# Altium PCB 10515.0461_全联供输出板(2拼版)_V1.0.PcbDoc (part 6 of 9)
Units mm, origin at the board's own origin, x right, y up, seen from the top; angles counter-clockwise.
Board outline 283.88 x 134.8 mm, 2 copper layers (Top Layer, Bottom Layer); 298 components, 0 nets, 1264 pads, 970 vias.
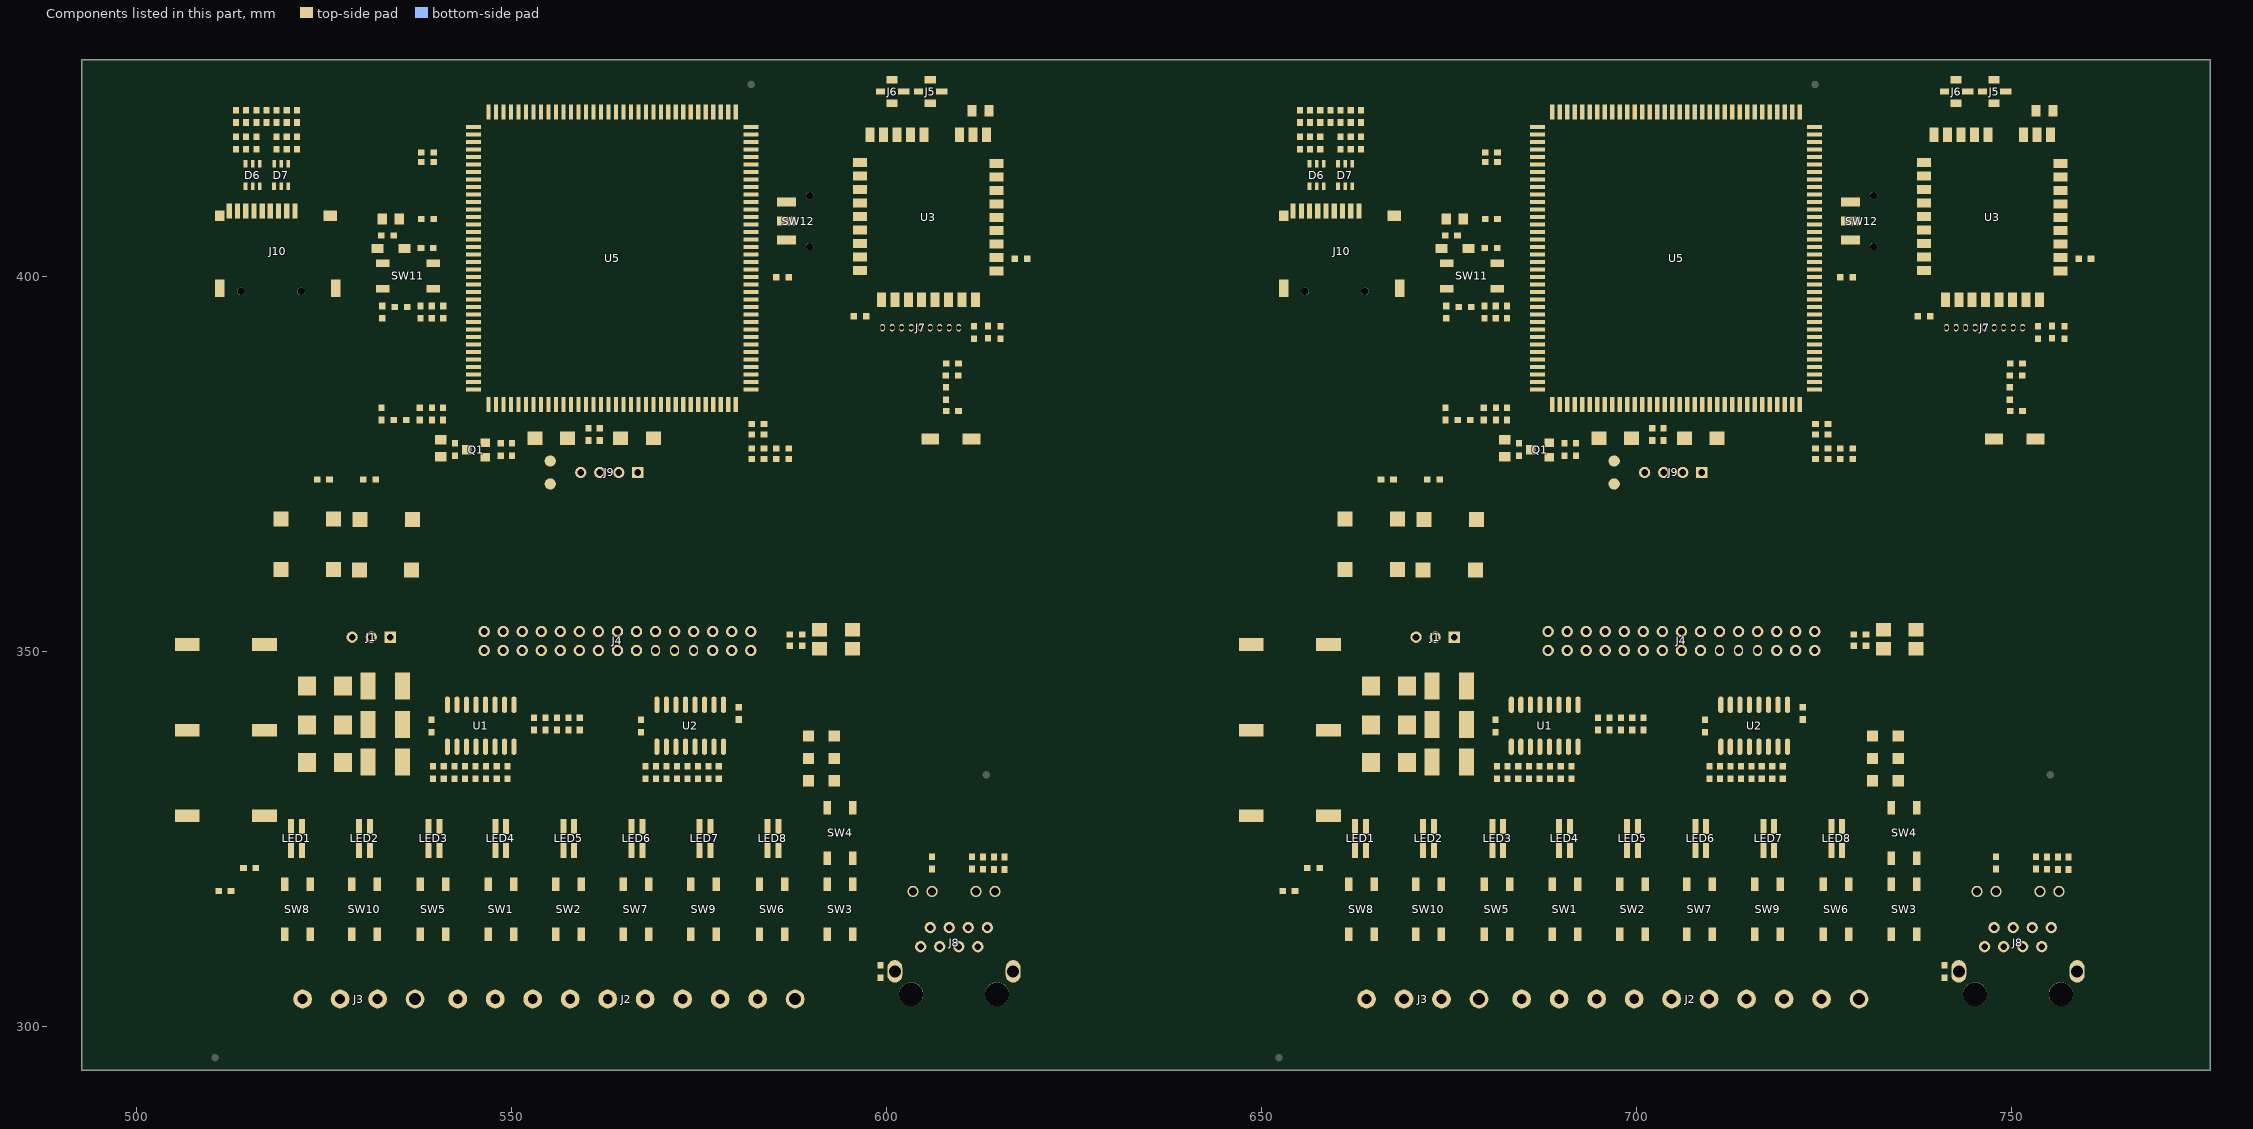
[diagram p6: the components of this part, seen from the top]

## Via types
v1: diameter 0.7, hole 0.4, Top Layer to Bottom Layer, tented both sides, 970 vias

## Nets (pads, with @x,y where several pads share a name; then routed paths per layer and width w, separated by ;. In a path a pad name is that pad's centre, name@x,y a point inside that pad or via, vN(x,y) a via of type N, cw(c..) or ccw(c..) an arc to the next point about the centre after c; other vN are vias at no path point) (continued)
copper on no net: (continued)
  Top Layer w0.8: 506.399,328.353 ccw(c505.631,329.121) 506.717,329.121 ccw(c507.803,329.121) 507.035,328.353 ; 506.399,339.147 cw(c505.631,338.379) 506.717,338.379 cw(c507.803,338.379) 507.035,339.147 ; 506.399,339.783 ccw(c505.631,340.551) 506.717,340.551 ccw(c507.803,340.551) 507.035,339.783 ; 506.399,350.577 cw(c505.631,349.809) 506.717,349.809 cw(c507.803,349.809) 507.035,350.577 ; v1@506.807,348.943 ccw(c507.913,348.943) 507.131,348.161 ; 507.199,339.147 cw(c505.878,337.826) 507.746,337.826 ; 507.199,339.783 ccw(c505.878,341.104) 507.746,341.104 ; 507.227,328.379 ccw(c506.061,329.766) 507.873,329.766 507.873,328.877 507.031,328.035 506.717,328.035 ; 507.364,328.35 cw(c507.978,327.086) 508.971,328.08 ; 507.517,350.445 cw(c507.517,349.532) 508.162,350.178 ; 507.613,327.595 cw(c507.828,326.618) 508.535,327.326 ; 507.746,329.766 507.746,344.879 ; 507.746,346.53 507.746,347.546 ; 507.835,327.717 cw(c508.603,326.949) 508.603,328.035 cw(c508.603,329.121) 507.835,328.353 ; 507.873,329.178 509.016,328.035 ; 507.873,344.879 510.032,347.038 ; 507.877,328.305 ccw(c509.524,329.536) 509.524,327.48 ; 507.967,350.895 ccw(c509.227,350.895) 508.336,350.004 ; 507.98,346.764 cw(c508.762,345.982) v1@508.762,347.088 ; 508,346.784 cw(c508.735,346.049) v1@508.763,347.088 ; 508,347.292 ccw(c508.735,348.027) v1@508.763,346.988 ; 508.817,349.523 cw(c507.601,348.308) v1@509.32,348.308 ; v1@509.27,348.358 cw(c509.27,346.639) 510.485,347.855 ; 509.668,346.674 cw(c510.667,345.676) v1@510.667,347.088 ; 509.715,346.721 cw(c510.605,345.83) v1@510.67,347.088 ; 509.848,348.492 ccw(c510.413,349.057) v1@510.413,348.258 ; v1@510.109,328.035 ccw(c511.083,328.035) 510.394,327.346 ; v1@510.163,328.085 cw(c510.107,327.298) 510.896,327.298 ; v1@510.194,328.07 cw(c508.501,326.377) 510.896,326.377 ; v1@510.208,328.024 cw(c509.524,328.182) 509.524,327.48 ; 510.286,303.731 510.286,304.366 ; 510.286,316.61 cw(c512.253,316.61) 510.862,318 ; 510.286,317.169 cw(c511.173,317.169) 510.86,317.999 ; 510.286,319.4 ccw(c512.253,319.4) 510.862,318.01 ; v1@510.286,348.054 507.445,350.895 506.717,350.895 506.717,348.575 507.746,347.546 ; 510.858,318.011 cw(c510.89,318.615) 510.286,318.615 ; 510.896,326.845 510.261,327.48 509.524,327.48 ; 511.048,398.408 511.048,406.601 ; 511.048,408.06 511.048,406.601 ; v1(511.429,347.038) 508.254,347.038 ; 512.699,300.937 510.286,303.35 510.286,302.588 ; 513.08,336.37 513.842,337.132 ; 513.842,300.937 536.321,300.937 537.09,301.706 ; v1(514.223,323.035) 514.223,308.176 ; 514.789,307.61 cw(c514.338,307.16) v1@514.975,307.16 ; v1@514.881,307.138 ccw(c515.874,307.637) 515.874,306.525 ; v1@514.904,307.115 cw(c515.39,308.176) 514.223,308.176 ; v1@514.925,307.21 cw(c514.925,306.573) 515.376,307.023 ; 515.377,338.667 cw(c516.217,337.827) 516.217,339.015 ; 515.479,338.769 ccw(c514.782,339.465) 515.767,339.465 ; 515.707,338.783 ccw(c515.707,339.691) 516.537,339.323 ; 515.806,339.647 cw(c514.477,340.236) 514.477,338.783 ; 515.849,326.81 cw(c516.725,326.81) 516.389,327.619 ; 515.849,330.011 ccw(c518.193,330.011) 516.535,328.353 ; 515.874,339.173 ccw(c513.969,337.55) 513.969,340.053 ; 515.882,321.058 ccw(c514.369,322.571) 516.509,322.571 ; 515.886,321.059 ccw(c515.854,321.713) 516.509,321.713 ; 515.893,321.053 ccw(c517.041,321.053) 516.229,320.241 ; 515.899,328.353 ccw(c514.732,329.52) 516.382,329.52 ; 515.899,339.147 ccw(c515.131,338.379) 515.131,339.465 ccw(c515.131,340.551) 515.899,339.783 ; 516.382,327.606 516.382,333.576 ; 516.699,328.353 ccw(c515.931,329.121) 517.017,329.121 ccw(c518.103,329.121) 517.335,328.353 ; 516.699,350.577 cw(c515.931,349.809) 517.017,349.809 cw(c518.103,349.809) 517.335,350.577 ; 517.271,332.814 519.049,334.592 ; 517.499,328.353 ccw(c516.822,329.03) 517.779,329.03 ; 517.499,350.577 cw(c516.822,349.9) 517.779,349.9 ; 517.525,308.049 516.636,308.938 516.636,319.835 515.849,320.622 ; 517.57,339.712 cw(c519.925,337.357) 519.925,340.688 ; 517.779,329.213 ccw(c518.995,329.213) 518.135,328.353 ; 517.779,347.927 519.811,345.895 ; 517.779,349.717 cw(c518.995,349.717) 518.135,350.577 ; 517.951,338.91 ccw(c517.951,344.765) 522.091,340.625 ; 517.976,351.316 ccw(c518.232,351.999) 518.748,351.483 ; 518.135,351.213 ccw(c518.903,351.981) 518.903,350.895 ccw(c518.903,349.809) 518.135,350.577 ; 518.267,339.465 cw(c519.945,339.465) 518.758,340.651 ; 518.668,345.336 517.779,346.225 517.779,347.419 ; 519.068,367.726 cw(c520.062,367.037) 520.062,368.247 ; 519.238,335.862 cw(c519.238,331.828) 522.091,334.681 ; 519.238,346.022 cw(c519.238,341.988) 522.091,344.841 ; 519.291,339.465 ccw(c519.291,343.425) 522.091,340.625 ; 519.373,361.022 cw(c517.704,359.353) 520.065,359.353 ; 519.484,334.592 ccw(c519.484,338.279) 522.091,335.672 ; 519.484,344.752 ccw(c519.484,348.439) 522.091,345.832 ; 519.545,340.688 cw(c519.545,337.088) 522.091,339.634 ; 519.656,360.457 ccw(c520.681,359.432) 519.232,359.432 ccw(c517.783,359.432) 518.808,360.457 ; 519.656,361.305 cw(c520.681,362.33) 519.232,362.33 cw(c517.783,362.33) 518.808,361.305 ccw(c516.692,363.421) 519.684,363.421 ; 519.656,368.036 ccw(c520.681,369.061) 520.681,367.612 ccw(c520.681,366.163) 519.656,367.188 ccw(c520.681,366.163) 519.232,366.163 ccw(c517.783,366.163) 518.808,367.188 cw(c516.692,365.072) 519.684,365.072 ; 519.684,358.341 ccw(c516.692,358.341) 518.808,360.457 ; 519.684,367.612 519.684,354.531 ; 519.725,367.271 cw(c521.589,365.981) 521.589,368.247 ; 519.882,338.91 ccw(c519.882,342.834) 522.656,340.059 cw(c521.222,341.494) 521.222,339.465 ; 520.065,357.421 ccw(c515.772,357.421) 518.808,360.457 ; 520.243,338.91 cw(c520.243,341.891) 518.135,339.783 ccw(c518.903,340.551) 518.903,339.465 ccw(c518.903,338.379) 518.135,339.147 ; 520.323,340.053 ccw(c520.323,336.959) 518.135,339.147 ; 520.323,351.483 ccw(c520.323,348.389) 518.135,350.577 ; 520.71,340.053 ccw(c520.71,342.006) 522.091,340.625 ; 520.74,340.053 cw(c520.74,338.143) 522.091,339.494 ; 521.17,335.862 cw(c521.17,333.76) 522.656,335.246 ; 521.17,346.022 cw(c521.17,343.92) 522.656,345.406 ; 521.415,334.592 ccw(c521.415,336.348) 522.656,335.106 ; 521.415,344.752 ccw(c521.415,346.508) 522.656,345.266 ; 521.437,338.91 517.572,338.91 517.017,339.465 ; 521.462,356.288 cw(c521.921,356.288) v1@521.833,356.739 ; 521.462,356.6 cw(c523.076,356.6) 521.935,357.741 cw(c522.769,356.907) 522.769,358.087 ; 521.462,357.489 ccw(c522.642,357.489) v1@521.808,356.655 ; 521.476,340.688 cw(c521.476,339.019) 522.656,340.199 ; 521.813,338.91 ccw(c521.813,340.902) 523.222,339.494 ; 521.856,340.688 ccw(c521.856,335.426) 518.135,339.147 ; 521.971,335.862 518.668,335.862 517.652,334.846 ; 521.971,346.022 518.668,346.022 517.779,346.911 517.779,347.419 ; v1(521.97,357.706) v1@521.97,356.563 ; v1(521.97,410.538) 527.431,410.538 ; v1@522.016,357.726 ccw(c521.462,357.482) 521.462,358.087 ; 522.072,334.592 519.049,334.592 ; 522.072,344.752 517.779,344.752 517.017,345.514 517.017,346.657 ; 522.09,303.604 514.858,303.604 ; 522.091,334.611 ccw(c520.725,333.245) 520.725,335.176 ccw(c520.725,337.108) 522.091,335.742 ; 522.091,344.771 ccw(c520.725,343.405) 520.725,345.336 ccw(c520.725,347.268) 522.091,345.902 ; 522.098,340.688 518.795,340.688 517.572,339.465 517.017,339.465 ; 522.187,358.087 cw(c522.187,356.907) v1@523.021,357.741 ; 522.58,340.053 518.414,340.053 ; 522.656,335.176 517.982,335.176 517.652,334.846 ; 522.656,340.129 521.992,339.465 517.017,339.465 ; 522.656,345.336 517.83,345.336 517.017,346.149 517.017,346.657 ; v1@522.951,357.741 cw(c523.785,356.907) 523.785,358.087 ; 523.255,356.563 ccw(c523.255,357.31) v1@523.783,356.782 ; 523.33,358.087 cw(c523.33,356.907) v1@524.164,357.741 ; 523.374,351.236 ccw(c522.776,350.638) 522.776,351.483 528.32,351.483 528.701,351.864 ; 523.494,370.152 523.494,372.386 524.027,372.919 ; 523.494,371.708 cw(c525.201,371.708) 523.994,372.915 ; 523.494,372.191 cw(c524.266,372.191) 523.992,372.913 ; 523.494,374.13 ccw(c525.201,374.13) 523.994,372.924 ; v1@523.713,356.782 ccw(c524.241,357.31) 524.241,356.563 ; 523.748,371.422 519.938,367.612 519.232,367.612 ; 524.027,370.685 521.589,368.247 ; 524.027,384.63 525.043,385.646 528.193,385.646 528.828,386.281 528.828,386.916 ; 524.856,358.56 ccw(c522.925,360.49) 525.636,360.81 ; 525.569,407.849 cw(c525.059,407.339) 525.78,407.339 cw(c526.501,407.339) 525.991,407.849 ; 525.678,368.466 ccw(c527.086,368.466) 526.091,367.471 ; 525.678,370.397 ccw(c529.017,370.397) 526.656,368.036 cw(c527.681,369.061) 526.232,369.061 cw(c524.783,369.061) 525.808,368.036 ccw(c523.115,370.729) 526.923,370.729 ; 525.678,372.438 526.923,371.193 526.923,361.897 ; 525.678,376.459 cw(c527.639,376.459) v1@526.253,377.845 ; 525.678,379.161 ccw(c527.639,379.161) v1@526.253,377.775 ; 525.712,372.924 ccw(c524.628,374.008) 526.161,374.008 ; 525.713,372.925 ccw(c525.252,373.708) 526.161,373.708 ; 525.78,361.333 525.78,367.612 526.232,367.612 ; 525.78,363.421 ccw(c528.772,363.421) 526.656,361.305 cw(c527.681,362.33) 526.232,362.33 cw(c524.783,362.33) 525.808,361.305 ccw(c523.115,363.998) 526.923,363.998 ; 525.78,365.072 cw(c528.772,365.072) 526.656,367.188 ccw(c527.681,366.163) 526.232,366.163 ccw(c524.783,366.163) 525.808,367.188 cw(c523.115,364.495) 526.923,364.495 ; 525.78,399.391 ccw(c527.018,399.391) 526.142,398.516 ; 525.78,401.088 cw(c527.394,401.088) v1@526.253,402.229 ; 525.78,401.323 ccw(c528.949,401.323) 526.708,399.082 ; 525.78,403.3 ccw(c527.394,403.3) v1@526.253,402.159 ; 525.78,403.628 cw(c527.394,403.628) v1@526.253,404.769 ; 525.78,405.84 ccw(c527.394,405.84) v1@526.253,404.699 ; 525.78,408.06 525.78,406.601 ; 525.971,373.518 ccw(c526.57,372.919) 525.723,372.919 ccw(c526.992,372.919) 526.095,372.022 ; 526.022,359.726 ccw(c525.011,360.737) 526.431,360.905 ; 526.042,382.733 cw(c526.542,382.233) v1@526.542,382.94 ; 526.161,351.483 526.542,351.864 528.701,351.864 ; 526.232,359.936 524.383,358.087 521.462,358.087 ; 526.232,371.884 526.232,367.612 ; 526.373,360.74 ccw(c525.047,362.066) 526.923,362.066 ; 526.373,367.471 ccw(c525.047,368.797) 526.923,368.797 ; 526.373,367.753 cw(c525.047,366.427) 526.923,366.427 ; 526.421,382.477 ccw(c526.008,382.89) v1@526.592,382.89 ; v1@526.492,382.887 cw(c527.1,382.929) 526.669,383.36 ; v1@526.507,382.925 cw(c527.556,381.876) 527.556,383.36 ; v1@526.542,382.84 ccw(c526.542,383.425) 526.955,383.011 ; 526.542,398.408 525.78,399.17 525.78,406.601 ; 526.78,361.125 cw(c527.413,361.407) 526.923,361.897 ; 527.05,386.281 528.193,387.424 528.193,395.044 529.184,396.035 532.715,396.035 ; 527.304,383.36 526.161,382.217 526.161,373.708 ; 527.456,335.246 cw(c528.672,334.471) 528.672,335.913 ; 527.456,345.336 528.041,344.752 530.182,344.752 ; 527.489,345.369 530.799,345.369 530.182,344.752 ; 528.022,334.611 cw(c529.388,333.245) 529.388,335.176 cw(c529.388,337.108) 528.022,335.742 ; 528.022,339.564 cw(c529.388,338.198) 529.388,340.129 cw(c529.388,342.061) 528.022,340.695 ; 528.022,344.771 cw(c529.466,343.327) 529.466,345.369 ; 528.022,345.902 ccw(c529.31,347.189) 529.31,345.369 ; 528.082,345.764 ccw(c530.182,347.435) 530.182,344.752 ; 528.088,340.551 ccw(c530.145,342.152) 530.145,339.545 528.041,339.545 527.456,340.129 530.729,340.129 ; 528.131,334.816 cw(c530.131,333.541) 530.131,335.913 528.193,335.913 527.456,335.176 530.729,335.176 ; 528.828,409.268 527.558,410.538 527.431,410.538 ; 528.907,344.752 cw(c528.907,342.677) 530.374,344.144 ; 528.955,403.68 532.108,403.68 532.574,404.146 532.574,407.503 ; 528.963,383.241 cw(c529.463,382.741) v1@529.463,383.448 ; 528.996,339.545 cw(c528.996,337.596) 530.374,338.974 ; 529.03,335.913 ccw(c529.03,337.814) 530.374,336.47 ; 529.183,335.176 ccw(c529.183,336.861) 530.374,335.67 ; 529.183,340.129 ccw(c529.183,341.814) 530.374,340.623 ; 529.209,361.241 529.209,371.878 530.2,372.869 ; 529.209,363.308 ccw(c532.15,363.308) 530.07,361.228 cw(c531.095,362.253) 529.646,362.253 cw(c528.197,362.253) 529.222,361.228 ccw(c526.8,363.65) 530.225,363.65 ; 529.209,364.725 cw(c532.583,364.725) 530.197,367.111 ccw(c531.528,365.78) 529.646,365.78 ; 529.209,366.656 cw(c530.652,366.656) 529.632,367.676 ; 529.209,368.414 ccw(c530.652,368.414) 529.632,367.394 ; 529.209,370.345 ccw(c532.583,370.345) 530.197,367.959 cw(c531.222,368.984) 529.773,368.984 cw(c528.324,368.984) 529.349,367.959 ccw(c527.295,370.013) 530.2,370.013 ; 529.244,360.359 cw(c527.249,358.15) 530.225,358.15 ; v1(529.336,397.838) v1(528.828,398.346) 528.828,410.03 528.32,410.538 527.431,410.538 ; v1@529.413,383.398 cw(c530.12,383.398) 529.62,383.898 ; 529.517,335.176 cw(c529.517,333.964) 530.374,334.821 ; 529.517,340.129 cw(c529.517,338.917) 530.374,339.774 ; v1@529.54,374.474 ccw(c530.717,374.378) 529.882,373.543 ; 529.59,373.59 cw(c530.612,373.59) v1@530.178,374.515 ; 529.59,373.754 cw(c531.551,373.754) v1@530.164,375.14 ; 529.59,375.821 ccw(c531.551,375.821) v1@530.164,374.435 ; 529.59,376.456 ccw(c531.551,376.456) v1@530.164,375.07 ; v1@529.625,374.435 ccw(c528.239,375.821) 530.2,375.821 ; v1@529.625,374.505 cw(c528.239,373.119) 530.2,373.119 ; v1@529.625,375.07 ccw(c528.239,376.456) 530.2,376.456 ; v1@529.625,375.14 cw(c528.239,373.754) 530.2,373.754 ; 529.646,366.393 ccw(c528.631,366.393) 529.349,367.111 cw(c527.233,364.995) 530.225,364.995 ; 529.67,335.913 cw(c529.67,334.917) 530.374,335.621 ; 529.704,339.545 ccw(c529.704,340.493) 530.374,339.823 ; 529.773,371.916 cw(c531.115,371.916) 530.166,372.864 ; 529.773,372.292 cw(c530.386,372.292) 530.164,372.863 ; 529.78,360.952 cw(c528.875,359.951) 530.225,359.951 ; 529.787,360.663 ccw(c528.731,361.719) 530.225,361.719 ; 529.793,344.752 ccw(c529.793,345.574) 530.374,344.993 ; 529.872,373.553 cw(c529.187,372.869) 530.155,372.869 ; 530.225,368.476 530.225,361.383 ; 530.352,385.265 529.209,384.122 526.542,384.122 525.678,383.258 525.678,382.369 ; 530.352,386.134 cw(c531.328,386.134) v1@530.638,386.824 ; 530.352,387.444 ccw(c531.328,387.444) v1@530.638,386.754 ; 530.352,392.103 cw(c531.328,392.103) v1@530.638,392.793 ; 530.352,393.413 ccw(c531.328,393.413) v1@530.638,392.723 ; 530.374,344.944 ccw(c529.35,343.92) 529.35,345.369 ccw(c529.35,346.817) 530.374,345.793 ; v1@530.709,386.754 ccw(c530.343,387.119) 530.86,387.119 ; v1@530.709,386.824 cw(c530.343,386.459) 530.86,386.459 ; v1@530.709,392.723 ccw(c530.343,393.088) 530.86,393.088 ; v1@530.709,392.793 cw(c530.343,392.428) 530.86,392.428 ; 531.622,394.384 530.86,393.622 530.86,385.138 530.352,384.63 ; 531.851,379.804 532.638,380.591 532.638,380.82 ; 531.893,372.864 cw(c533.623,371.135) 533.623,373.581 ; 531.895,372.867 ccw(c532.662,372.652) 532.099,372.088 ; 532.167,403.821 ccw(c531.182,404.806) 532.574,404.806 ; 532.574,406.611 cw(c533.619,406.611) 532.88,407.349 ; 532.633,382.514 ccw(c530.783,384.364) 533.4,384.364 ; 532.793,398.348 539.493,398.348 541.149,398.348 541.528,398.727 541.528,403.172 540.943,403.757 539.521,403.757 ; 532.793,401.748 539.493,401.748 ; v1(533.4,392.758) 533.4,382.471 ; 534.226,405.458 535.305,405.458 535.708,405.055 535.708,403.68 ; 534.231,380.82 531.851,380.82 531.851,373.581 ; 534.264,396.035 532.715,396.035 ; 534.797,354.102 534.241,354.658 520.652,354.658 520.065,355.245 520.065,360.048 519.232,360.881 ; 534.974,346.593 ccw(c533.95,347.617) 535.399,347.617 ccw(c536.847,347.617) 535.823,346.593 ; 535,407.642 537.883,407.642 ; 535.399,345.369 535.399,348.275 537.21,350.086 ; 535.785,403.757 537.87,403.757 537.87,401.9 ; 535.925,368.12 cw(c535.925,366.793) 536.924,367.667 ; 535.947,380.82 537.718,380.82 539.33,380.82 540.816,380.82 ; 536.049,403.539 cw(c536.577,403.011) 536.577,403.757 ; 536.169,396.035 537.795,396.035 539.319,396.035 540.843,396.035 ; 536.194,358.264 cw(c539.186,358.264) 537.07,360.38 ccw(c538.095,359.355) 536.646,359.355 ccw(c535.197,359.355) 536.222,360.38 ; 536.194,363.344 ccw(c539.186,363.344) 537.07,361.228 cw(c537.788,361.946) 536.773,361.946 ; 536.194,364.689 cw(c539.619,364.689) 537.197,367.111 ccw(c538.222,366.086) 536.773,366.086 ccw(c535.324,366.086) 536.349,367.111 ccw(c535.324,366.086) 535.324,367.535 ccw(c535.324,368.984) 536.349,367.959 ; 536.194,366.62 cw(c537.688,366.62) 536.632,367.676 ; 536.194,366.956 536.194,355.928 536.448,355.674 539.115,355.674 551.18,355.674 ; 536.222,361.228 ccw(c534.891,362.559) 536.773,362.559 ; 536.321,367.14 ccw(c534.162,365.251) 534.162,368.12 ; 536.524,302.97 cw(c535.396,301.706) 537.09,301.706 ; 537.039,355.845 538.944,355.845 553.041,355.845 553.212,355.674 ; 537.09,303.604 537.09,301.706 ; 537.21,356.309 536.646,356.873 536.646,360.804 536.773,360.931 536.773,367.535 ; v1@537.265,339.594 cw(c537.451,338.838) 538.002,339.388 ; v1@537.277,339.595 cw(c537.277,338.345) 538.161,339.229 ; v1@537.311,339.508 ccw(c536.462,340.434) 537.718,340.434 ; 537.656,302.97 ccw(c538.784,301.706) 537.09,301.706 ; 537.718,340.09 cw(c538.668,340.09) v1@537.996,340.761 ; 537.718,340.118 cw(c538.601,340.118) v1@537.997,340.763 ; 537.718,341.362 ccw(c538.668,341.362) v1@537.996,340.691 ; 537.718,345.939 cw(c538.56,345.939) v1@538.205,346.702 ; 537.795,394.384 540.843,394.384 532.715,394.384 531.089,394.384 530.352,393.647 530.352,384.63 ; v1@537.983,340.737 ccw(c539.189,340.479) 538.317,339.607 ; v1@538.176,346.657 cw(c540.508,346.657) v1@538.859,348.306 ; v1@538.221,346.607 cw(c538.279,347.165) v1@537.718,347.165 ; 538.263,339.66 ccw(c539.292,340.688) 539.292,339.234 ; 538.624,348.071 cw(c539.623,347.073) v1@539.623,348.485 ; 538.64,348.087 ccw(c538.291,348.435) v1@538.784,348.435 ; v1@538.671,348.118 cw(c539.561,347.227) v1@539.626,348.485 ; 538.734,339.189 537.718,340.205 537.718,340.434 ; v1@538.816,347.397 cw(c539.627,347.796) v1@538.988,348.435 ; 539.292,339.189 538.201,339.189 537.718,339.672 537.718,340.434 ; 539.292,340.84 539.292,345.945 540.131,346.784 552.783,346.784 553.926,347.927 ; 539.292,345.26 540.308,346.276 540.766,346.276 ; 539.439,347.87 ccw(c538.874,348.435) v1@539.673,348.435 ; 539.623,346.276 540.766,346.276 ; 540.048,371.251 553.212,371.251 553.847,370.616 ; 540.537,378.204 540.537,380.541 ; 540.537,380.094 cw(c541.504,380.094) 540.821,380.777 ; 541.013,398.212 cw(c542.163,397.061) v1@542.163,398.688 ; 541.166,398.365 cw(c541.982,397.549) v1@542.171,398.687 ; 541.274,370.787 538.48,373.581 531.851,373.581 ; 541.528,400.05 ccw(c543.575,400.05) v1@542.128,398.603 ; 542.373,382.471 ccw(c542.373,383.218) v1@542.901,382.69 ; 542.777,303.604 542.777,307.054 541.782,308.049 516.763,308.049 515.849,308.963 515.849,320.622 ; v1@542.83,382.69 ccw(c543.358,383.218) 543.358,382.471 ; v1@544.576,382.725 544.322,382.471 540.816,382.471 539.33,382.471 537.718,382.471 533.4,382.471 ; v1(546.481,379.169) 546.481,377.817 546.59,377.709 548.513,377.709 ; 546.666,377.938 ccw(c547.221,378.493) 547.221,377.709 ; 551.024,352.626 ccw(c550.15,352.626) 550.768,353.244 ccw(c551.386,353.862) 551.386,352.988 ; 551.718,300.683 cw(c551.718,299.503) v1@552.553,300.337 ; v1@552.482,300.337 cw(c553.316,299.503) 553.316,300.683 ; 552.706,378.053 cw(c551.853,377.2) 553.06,377.2 cw(c554.267,377.2) 553.414,378.053 ; 552.958,341.133 554.482,341.133 556.006,341.133 557.53,341.133 559.054,341.133 ; v1@553.06,376.756 553.06,378.407 ; 553.094,353.76 cw(c551.961,352.626) 553.564,352.626 ; 553.67,349.83 cw(c553.052,349.212) 553.926,349.212 cw(c554.8,349.212) 554.182,349.83 ; 553.67,352.882 ccw(c553.052,353.5) 553.926,353.5 ccw(c554.8,353.5) 554.182,352.882 ; 553.926,350.086 553.926,347.244 552.958,346.276 540.766,346.276 ; 553.926,352.626 553.926,352.928 ; 557.208,302.973 cw(c556.052,301.692) 557.777,301.692 ; 557.777,303.604 557.777,301.692 ; 558.346,302.973 ccw(c559.502,301.692) 557.777,301.692 ; 564.014,374.082 ccw(c563.416,374.68) 564.261,374.68 ccw(c565.106,374.68) 564.508,374.082 ; 564.261,373.835 564.261,375.359 564.896,375.994 565.658,375.994 ; 564.511,374.08 cw(c564.903,374.463) 564.515,374.851 565.658,375.994 ; 564.611,373.835 cw(c567.296,373.835) 565.397,375.733 ; 567.048,374.082 ccw(c567.646,374.68) 567.646,373.835 ccw(c567.646,372.99) 567.048,373.588 ; 567.119,374.153 cw(c566.354,373.388) 567.436,373.388 ; v1@567.278,375.955 ccw(c567.589,376.349) 567.944,375.994 v1@568.858,376.908 ; v1@567.309,375.944 ccw(c567.309,377.356) 568.308,376.358 ; v1@567.401,376.086 cw(c568.833,374.653) 568.833,376.679 ccw(c568.833,376.186) 568.485,376.535 ; v1@567.421,375.994 ccw(c567.421,378.041) v1@568.868,376.594 ; 567.436,371.457 ccw(c564.423,371.457) 566.554,373.588 ; v1@567.754,376.439 cw(c568.486,375.706) v1@568.851,376.676 ; v1@567.898,376.609 ccw(c568.833,377.012) v1(568.833,375.994) ; v1@567.939,376.579 ccw(c568.051,377.715) v1@568.858,376.908 ; v1@567.979,376.594 ccw(c567.451,377.122) 568.198,377.122 ; v1@567.987,376.604 cw(c566.928,377.219) 566.928,375.994 ; 568.071,373.835 567.436,373.2 567.436,371.295 566.757,370.616 565.023,370.616 ; v1@568.198,376.783 cw(c569.471,376.783) 568.959,377.949 ; v1@568.793,375.964 cw(c569.367,376.399) v1@568.858,376.908 ; v1@568.804,376.588 cw(c569.609,377.747) 568.198,377.747 568.198,376.883 v1(567.309,375.994) 566.928,375.994 ; 583.629,375.613 v1(584.454,375.613) 585.279,375.613 ; 583.629,377.01 v1(584.454,377.01) 585.279,377.01 ; 586.93,377.01 586.93,375.613 586.93,374.407 ; 587.132,374.407 cw(c587.132,372.576) v1@588.426,373.87 ; 587.703,373.835 ccw(c587.703,375.666) v1@588.998,374.371 ; 587.767,374.407 cw(c587.767,372.576) v1@589.061,373.87 ; v1@588.341,373.84 cw(c588.962,373.783) v1(588.962,374.407) ; v1@588.752,374.617 cw(c587.97,373.835) v1@589.076,373.835 ; v1@601.041,373.84 cw(c601.599,373.782) 601.599,374.343 ; v1@601.056,373.87 cw(c602.197,372.729) v1@602.197,374.343 ; 601.074,307.285 616.864,307.285 ; v1@601.168,371.427 cw(c601.726,371.369) v1@601.726,371.93 ; v1@601.183,371.457 cw(c602.324,370.316) v1@602.324,371.93 ; v1@601.382,371.422 ccw(c601.382,373.036) v1@602.523,371.895 ; 601.498,306.861 cw(c602.523,305.836) 602.523,307.285 cw(c602.523,308.734) 601.498,307.709 ; v1@601.564,371.895 ccw(c602.705,373.036) 602.705,371.422 ; v1@601.818,373.87 cw(c602.959,372.729) 602.959,374.343 ; v1@601.945,371.457 cw(c603.086,370.316) 603.086,371.93 ; v1@602.072,374.435 ccw(c603.519,375.882) 603.519,373.835 ; v1@602.15,374.445 cw(c601.091,375.06) v1(601.091,373.835) ; v1@602.453,371.895 ccw(c603.594,373.036) 603.594,371.422 ; 605.006,378.179 cw(c606.783,378.348) 605.52,379.61 ; 605.058,371.93 cw(c605.058,370.75) v1@605.893,371.584 ; 605.155,376.981 cw(c606.666,376.981) 605.597,378.05 ; 605.155,377.772 605.155,379.244 ; 605.526,378.6 cw(c605.901,379.244) 605.155,379.244 ; 605.553,378.05 cw(c604.955,377.452) 605.8,377.452 cw(c606.645,377.452) 606.047,378.05 ; 605.553,378.544 ccw(c604.955,379.142) 605.8,379.142 ccw(c606.645,379.142) 606.047,378.544 ; 605.802,378.254 cw(c608.977,378.556) 606.722,380.811 ; v1@605.822,371.584 cw(c606.656,370.75) 606.656,371.93 ; 606.25,378.647 ccw(c606.25,380.262) 607.392,379.12 ; 606.513,380.019 ccw(c608.236,378.297) 605.8,378.297 ; 606.569,378.297 607.924,379.652 v1(607.924,380.693) ; 606.598,378.33 cw(c611.172,378.764) 607.923,382.013 ; 606.752,380.258 cw(c607.924,379.085) v1@607.924,380.743 ; 607.166,379.663 ccw(c608.531,378.297) 606.6,378.297 cw(c610.967,378.297) 607.879,381.385 ; 607.435,380.941 ccw(c606.363,382.013) 607.879,382.013 ; 607.876,385.202 607.876,388.315 ; v1@607.885,380.661 cw(c608.329,381.024) 607.924,381.43 605.8,379.306 605.8,378.297 ; 607.924,383.503 607.924,382.013 ; 609.335,381.085 cw(c606.548,378.297) 610.49,378.297 ccw(c608.559,378.297) 609.924,379.663 ; 609.575,380.845 611.29,379.13 ; 609.6,388.388 609.575,388.363 609.575,382.013 ; 609.619,382.013 ccw(c610.767,382.013) 609.955,381.201 ; v1@609.957,374.435 ccw(c608.364,376.027) 610.616,376.027 ; v1@609.957,374.505 cw(c608.364,372.913) 610.616,372.913 ; 610.18,380.976 cw(c607.501,378.297) 611.29,378.297 ; 610.616,376.911 cw(c612.226,376.911) 611.087,378.05 ; 610.616,378.971 610.616,373.073 609.473,371.93 609.092,371.93 ; 610.701,379.719 cw(c609.279,378.297) 611.29,378.297 ; 611.045,378.547 ccw(c610.474,379.13) 611.29,379.13 ; 611.124,377.051 cw(c612.536,377.051) 611.537,378.05 ; 611.493,378.05 cw(c610.91,377.467) 611.734,377.467 ; 611.493,378.544 ccw(c610.91,379.127) 611.734,379.127 ; 611.535,378.547 cw(c612.106,379.13) 611.29,379.13 ; 611.546,379.611 cw(c610.232,378.297) 612.09,378.297 ; 611.632,393.33 612.521,393.33 614.807,393.33 ; 611.734,377.437 cw(c612.6,377.437) 611.987,378.05 ; 611.734,379.157 ccw(c612.6,379.157) 611.987,378.544 ; 613.487,391.717 615.023,391.717 ; 616.44,306.861 ccw(c615.416,305.837) 615.416,307.285 ccw(c615.415,308.734) 616.44,307.709 ; 648.299,328.353 ccw(c647.531,329.121) 648.617,329.121 ccw(c649.703,329.121) 648.935,328.353 ; 648.299,339.147 cw(c647.531,338.379) 648.617,338.379 cw(c649.703,338.379) 648.935,339.147 ; 648.299,339.783 ccw(c647.531,340.551) 648.617,340.551 ccw(c649.703,340.551) 648.935,339.783 ; 648.299,350.577 cw(c647.531,349.809) 648.617,349.809 cw(c649.703,349.809) 648.935,350.577 ; v1@648.707,348.943 ccw(c649.813,348.943) 649.031,348.161 ; 649.099,339.147 cw(c647.778,337.826) 649.646,337.826 ; 649.099,339.783 ccw(c647.778,341.104) 649.646,341.104 ; 649.127,328.379 ccw(c647.961,329.766) 649.773,329.766 649.773,328.877 648.931,328.035 648.617,328.035 ; 649.264,328.35 cw(c649.878,327.086) 650.871,328.08 ; 649.417,350.445 cw(c649.417,349.532) 650.062,350.178 ; 649.513,327.595 cw(c649.728,326.618) 650.435,327.326 ; 649.646,329.766 649.646,344.879 ; 649.646,346.53 649.646,347.546 ; 649.735,327.717 cw(c650.503,326.949) 650.503,328.035 cw(c650.503,329.121) 649.735,328.353 ; 649.773,329.178 650.916,328.035 ; 649.773,344.879 651.932,347.038 ; 649.777,328.305 ccw(c651.424,329.536) 651.424,327.48 ; 649.867,350.895 ccw(c651.127,350.895) 650.236,350.004 ; 649.88,346.764 cw(c650.662,345.982) v1@650.662,347.088 ; 649.9,346.784 cw(c650.635,346.049) v1@650.663,347.088 ; 649.9,347.292 ccw(c650.635,348.027) v1@650.663,346.988 ; 650.717,349.523 cw(c649.501,348.308) v1@651.22,348.308 ; v1@651.17,348.358 cw(c651.17,346.639) 652.385,347.855 ; 651.568,346.674 cw(c652.567,345.676) v1@652.567,347.088 ; 651.615,346.721 cw(c652.505,345.83) v1@652.57,347.088 ; 651.748,348.492 ccw(c652.313,349.057) v1@652.313,348.258 ; v1@652.009,328.035 ccw(c652.983,328.035) 652.294,327.346 ; v1@652.063,328.085 cw(c652.007,327.298) 652.796,327.298 ; v1@652.094,328.07 cw(c650.401,326.377) 652.796,326.377 ; v1@652.108,328.024 cw(c651.424,328.182) 651.424,327.48 ; 652.186,303.731 652.186,304.366 ; 652.186,316.61 cw(c654.153,316.61) 652.762,318 ; 652.186,317.169 cw(c653.073,317.169) 652.76,317.999 ; 652.186,319.4 ccw(c654.153,319.4) 652.762,318.01 ; v1@652.186,348.054 649.345,350.895 648.617,350.895 648.617,348.575 649.646,347.546 ; 652.758,318.011 cw(c652.79,318.615) 652.186,318.615 ; 652.796,326.845 652.161,327.48 651.424,327.48 ; 652.948,398.408 652.948,406.601 ; 652.948,408.06 652.948,406.601 ; v1(653.329,347.038) 650.154,347.038 ; 654.599,300.937 652.186,303.35 652.186,302.588 ; 654.98,336.37 655.742,337.132 ; 655.742,300.937 678.221,300.937 678.99,301.706 ; v1(656.123,323.035) 656.123,308.176 ; 656.689,307.61 cw(c656.238,307.16) v1@656.875,307.16 ; v1@656.78,307.138 ccw(c657.774,307.637) 657.774,306.525 ; v1@656.804,307.115 cw(c657.29,308.176) 656.123,308.176 ; v1@656.825,307.21 cw(c656.825,306.573) 657.276,307.023 ; 657.277,338.667 cw(c658.117,337.827) 658.117,339.015 ; 657.378,338.769 ccw(c656.682,339.465) 657.667,339.465 ; 657.607,338.783 ccw(c657.607,339.691) 658.437,339.323 ; 657.706,339.647 cw(c656.377,340.236) 656.377,338.783 ; 657.749,326.81 cw(c658.625,326.81) 658.289,327.619 ; 657.749,330.011 ccw(c660.093,330.011) 658.435,328.353 ; 657.774,339.173 ccw(c655.869,337.55) 655.869,340.053 ; 657.782,321.058 ccw(c656.269,322.571) 658.409,322.571 ; 657.786,321.059 ccw(c657.754,321.713) 658.409,321.713 ; 657.793,321.053 ccw(c658.941,321.053) 658.129,320.241 ; 657.799,328.353 ccw(c656.632,329.52) 658.282,329.52 ; 657.799,339.147 ccw(c657.031,338.379) 657.031,339.465 ccw(c657.031,340.551) 657.799,339.783 ; 658.282,327.606 658.282,333.576 ; 658.599,328.353 ccw(c657.831,329.121) 658.917,329.121 ccw(c660.003,329.121) 659.235,328.353 ; 658.599,350.577 cw(c657.831,349.809) 658.917,349.809 cw(c660.003,349.809) 659.235,350.577 ; 659.171,332.814 660.949,334.592 ; 659.399,328.353 ccw(c658.722,329.03) 659.679,329.03 ; 659.399,350.577 cw(c658.722,349.9) 659.679,349.9 ; 659.425,308.049 658.536,308.938 658.536,319.835 657.749,320.622 ; 659.47,339.712 cw(c661.825,337.357) 661.825,340.688 ; 659.679,329.213 ccw(c660.895,329.213) 660.035,328.353 ; 659.679,347.927 661.711,345.895 ; 659.679,349.717 cw(c660.895,349.717) 660.035,350.577 ; 659.851,338.91 ccw(c659.851,344.765) 663.991,340.625 ; 659.876,351.316 ccw(c660.132,351.999) 660.648,351.483 ; 660.035,351.213 ccw(c660.803,351.981) 660.803,350.895 ccw(c660.803,349.809) 660.035,350.577 ; 660.167,339.465 cw(c661.845,339.465) 660.658,340.651 ; 660.568,345.336 659.679,346.225 659.679,347.419 ; 660.968,367.726 cw(c661.962,367.037) 661.962,368.247 ; 661.138,335.862 cw(c661.138,331.828) 663.991,334.681 ; 661.138,346.022 cw(c661.138,341.988) 663.991,344.841 ; 661.191,339.465 ccw(c661.191,343.425) 663.991,340.625 ; 661.273,361.022 cw(c659.604,359.353) 661.965,359.353 ; 661.384,334.592 ccw(c661.384,338.279) 663.991,335.672 ; 661.384,344.752 ccw(c661.384,348.439) 663.991,345.832 ; 661.445,340.688 cw(c661.445,337.088) 663.991,339.634 ; 661.556,360.457 ccw(c662.581,359.432) 661.132,359.432 ccw(c659.683,359.432) 660.708,360.457 ; 661.556,361.305 cw(c662.581,362.33) 661.132,362.33 cw(c659.683,362.33) 660.708,361.305 ccw(c658.592,363.421) 661.584,363.421 ; 661.556,368.036 ccw(c662.581,369.061) 662.581,367.612 ccw(c662.581,366.163) 661.556,367.188 ccw(c662.581,366.163) 661.132,366.163 ccw(c659.683,366.163) 660.708,367.188 cw(c658.592,365.072) 661.584,365.072 ; 661.584,358.341 ccw(c658.592,358.341) 660.708,360.457 ; 661.584,367.612 661.584,354.531 ; 661.625,367.271 cw(c663.489,365.981) 663.489,368.247 ; 661.782,338.91 ccw(c661.782,342.834) 664.556,340.059 cw(c663.122,341.494) 663.122,339.465 ; 661.965,357.421 ccw(c657.672,357.421) 660.708,360.457 ; 662.143,338.91 cw(c662.143,341.891) 660.035,339.783 ccw(c660.803,340.551) 660.803,339.465 ccw(c660.803,338.379) 660.035,339.147 ; 662.223,340.053 ccw(c662.223,336.959) 660.035,339.147 ; 662.223,351.483 ccw(c662.223,348.389) 660.035,350.577 ; 662.61,340.053 ccw(c662.61,342.006) 663.991,340.625 ; 662.64,340.053 cw(c662.64,338.143) 663.991,339.494 ; 663.07,335.862 cw(c663.07,333.76) 664.556,335.246 ; 663.07,346.022 cw(c663.07,343.92) 664.556,345.406 ; 663.315,334.592 ccw(c663.315,336.348) 664.556,335.106 ; 663.315,344.752 ccw(c663.315,346.508) 664.556,345.266 ; 663.337,338.91 659.472,338.91 658.917,339.465 ; 663.362,356.288 cw(c663.821,356.288) v1@663.733,356.739 ; 663.362,356.6 cw(c664.976,356.6) 663.835,357.741 cw(c664.669,356.907) 664.669,358.087 ; 663.362,357.489 ccw(c664.542,357.489) v1@663.708,356.655 ; 663.376,340.688 cw(c663.376,339.019) 664.556,340.199 ; 663.713,338.91 ccw(c663.713,340.902) 665.122,339.494 ; 663.756,340.688 ccw(c663.756,335.426) 660.035,339.147 ; v1(663.87,357.706) v1@663.87,356.563 ; v1(663.87,410.538) 669.331,410.538 ; 663.871,335.862 660.568,335.862 659.552,334.846 ; 663.871,346.022 660.568,346.022 659.679,346.911 659.679,347.419 ; v1@663.916,357.726 ccw(c663.362,357.482) 663.362,358.087 ; 663.972,334.592 660.949,334.592 ; 663.972,344.752 659.679,344.752 658.917,345.514 658.917,346.657 ; 663.99,303.604 656.758,303.604 ; 663.991,334.611 ccw(c662.625,333.245) 662.625,335.176 ccw(c662.625,337.108) 663.991,335.742 ; 663.991,344.771 ccw(c662.625,343.405) 662.625,345.336 ccw(c662.625,347.268) 663.991,345.902 ; 663.998,340.688 660.695,340.688 659.472,339.465 658.917,339.465 ; 664.087,358.087 cw(c664.087,356.907) v1@664.921,357.741 ; 664.48,340.053 660.314,340.053 ; 664.556,335.176 659.882,335.176 659.552,334.846 ; 664.556,340.129 663.892,339.465 658.917,339.465 ; 664.556,345.336 659.73,345.336 658.917,346.149 658.917,346.657 ; v1@664.851,357.741 cw(c665.685,356.907) 665.685,358.087 ; 665.155,356.563 ccw(c665.155,357.31) v1@665.683,356.782 ; 665.23,358.087 cw(c665.23,356.907) v1@666.064,357.741 ; 665.274,351.236 ccw(c664.676,350.638) 664.676,351.483 670.22,351.483 670.601,351.864 ; 665.394,370.152 665.394,372.386 665.927,372.919 ; 665.394,371.708 cw(c667.101,371.708) 665.894,372.915 ; 665.394,372.191 cw(c666.166,372.191) 665.892,372.913 ; 665.394,374.13 ccw(c667.101,374.13) 665.894,372.924 ; v1@665.613,356.782 ccw(c666.14,357.31) 666.14,356.563 ; 665.648,371.422 661.838,367.612 661.132,367.612 ; 665.927,370.685 663.489,368.247 ; 665.927,384.63 666.943,385.646 670.093,385.646 670.728,386.281 670.728,386.916 ; 666.756,358.56 ccw(c664.825,360.49) 667.536,360.81 ; 667.469,407.849 cw(c666.959,407.339) 667.68,407.339 cw(c668.401,407.339) 667.891,407.849 ; 667.578,368.466 ccw(c668.986,368.466) 667.991,367.471 ; 667.578,370.397 ccw(c670.917,370.397) 668.556,368.036 cw(c669.581,369.061) 668.132,369.061 cw(c666.683,369.061) 667.708,368.036 ccw(c665.015,370.729) 668.823,370.729 ; 667.578,372.438 668.823,371.193 668.823,361.897 ; 667.578,376.459 cw(c669.539,376.459) v1@668.153,377.845 ; 667.578,379.161 ccw(c669.539,379.161) v1@668.153,377.775 ; 667.612,372.924 ccw(c666.528,374.008) 668.061,374.008 ; 667.613,372.925 ccw(c667.152,373.708) 668.061,373.708 ; 667.68,361.333 667.68,367.612 668.132,367.612 ; 667.68,363.421 ccw(c670.672,363.421) 668.556,361.305 cw(c669.581,362.33) 668.132,362.33 cw(c666.683,362.33) 667.708,361.305 ccw(c665.015,363.998) 668.823,363.998 ; 667.68,365.072 cw(c670.672,365.072) 668.556,367.188 ccw(c669.581,366.163) 668.132,366.163 ccw(c666.683,366.163) 667.708,367.188 cw(c665.015,364.495) 668.823,364.495 ; 667.68,399.391 ccw(c668.918,399.391) 668.042,398.516 ; 667.68,401.088 cw(c669.294,401.088) v1@668.153,402.229 ; 667.68,401.323 ccw(c670.849,401.323) 668.608,399.082 ; 667.68,403.3 ccw(c669.294,403.3) v1@668.153,402.159 ; 667.68,403.628 cw(c669.294,403.628) v1@668.153,404.769 ; 667.68,405.84 ccw(c669.294,405.84) v1@668.153,404.699 ; 667.68,408.06 667.68,406.601 ; 667.871,373.518 ccw(c668.47,372.919) 667.623,372.919 ccw(c668.892,372.919) 667.995,372.022 ; 667.922,359.726 ccw(c666.911,360.737) 668.331,360.905 ; 667.942,382.733 cw(c668.442,382.233) v1@668.442,382.94 ; 668.061,351.483 668.442,351.864 670.601,351.864 ; 668.132,359.936 666.283,358.087 663.362,358.087 ; 668.132,371.884 668.132,367.612 ; 668.273,360.74 ccw(c666.947,362.066) 668.823,362.066 ; 668.273,367.471 ccw(c666.947,368.797) 668.823,368.797 ; 668.273,367.753 cw(c666.947,366.427) 668.823,366.427 ; 668.321,382.477 ccw(c667.908,382.89) v1@668.492,382.89 ; v1@668.392,382.887 cw(c669,382.929) 668.569,383.36 ; v1@668.407,382.925 cw(c669.456,381.876) 669.456,383.36 ; v1@668.442,382.84 ccw(c668.442,383.425) 668.855,383.011 ; 668.442,398.408 667.68,399.17 667.68,406.601 ; 668.68,361.125 cw(c669.313,361.407) 668.823,361.897 ; 668.95,386.281 670.093,387.424 670.093,395.044 671.084,396.035 674.615,396.035 ; 669.204,383.36 668.061,382.217 668.061,373.708 ; 669.356,335.246 cw(c670.572,334.471) 670.572,335.913 ; 669.356,345.336 669.941,344.752 672.082,344.752 ; 669.389,345.369 672.699,345.369 672.082,344.752 ; 669.922,334.611 cw(c671.288,333.245) 671.288,335.176 cw(c671.288,337.108) 669.922,335.742 ; 669.922,339.564 cw(c671.288,338.198) 671.288,340.129 cw(c671.288,342.061) 669.922,340.695 ; 669.922,344.771 cw(c671.366,343.327) 671.366,345.369 ; 669.922,345.902 ccw(c671.21,347.189) 671.21,345.369 ; 669.982,345.764 ccw(c672.082,347.435) 672.082,344.752 ; 669.988,340.551 ccw(c672.045,342.152) 672.045,339.545 669.941,339.545 669.356,340.129 672.629,340.129 ; 670.031,334.816 cw(c672.031,333.541) 672.031,335.913 670.093,335.913 669.356,335.176 672.629,335.176 ; 670.728,409.268 669.458,410.538 669.331,410.538 ; 670.807,344.752 cw(c670.807,342.677) 672.274,344.144 ; 670.855,403.68 674.008,403.68 674.474,404.146 674.474,407.503 ; 670.863,383.241 cw(c671.363,382.741) v1@671.363,383.448 ; 670.896,339.545 cw(c670.896,337.596) 672.274,338.974 ; 670.93,335.913 ccw(c670.93,337.814) 672.274,336.47 ; 671.083,335.176 ccw(c671.083,336.861) 672.274,335.67 ; 671.083,340.129 ccw(c671.083,341.814) 672.274,340.623 ; 671.109,361.241 671.109,371.878 672.1,372.869 ; 671.109,363.308 ccw(c674.05,363.308) 671.97,361.228 cw(c672.995,362.253) 671.546,362.253 cw(c670.097,362.253) 671.122,361.228 ccw(c668.7,363.65) 672.125,363.65 ; 671.109,364.725 cw(c674.483,364.725) 672.097,367.111 ccw(c673.428,365.78) 671.546,365.78 ; 671.109,366.656 cw(c672.552,366.656) 671.532,367.676 ; 671.109,368.414 ccw(c672.552,368.414) 671.532,367.394 ; 671.109,370.345 ccw(c674.483,370.345) 672.097,367.959 cw(c673.122,368.984) 671.673,368.984 cw(c670.224,368.984) 671.249,367.959 ccw(c669.195,370.013) 672.1,370.013 ; 671.144,360.359 cw(c669.149,358.15) 672.125,358.15 ; v1(671.236,397.838) v1(670.728,398.346) 670.728,410.03 670.22,410.538 669.331,410.538 ; v1@671.313,383.398 cw(c672.02,383.398) 671.52,383.898 ; 671.417,335.176 cw(c671.417,333.964) 672.274,334.821 ; 671.417,340.129 cw(c671.417,338.917) 672.274,339.774 ; v1@671.44,374.474 ccw(c672.617,374.378) 671.782,373.543 ; 671.49,373.59 cw(c672.512,373.59) v1@672.078,374.515 ; 671.49,373.754 cw(c673.451,373.754) v1@672.064,375.14 ; 671.49,375.821 ccw(c673.451,375.821) v1@672.064,374.435 ; 671.49,376.456 ccw(c673.451,376.456) v1@672.064,375.07 ; v1@671.525,374.435 ccw(c670.139,375.821) 672.1,375.821 ; v1@671.525,374.505 cw(c670.139,373.119) 672.1,373.119 ; v1@671.525,375.07 ccw(c670.139,376.456) 672.1,376.456 ; v1@671.525,375.14 cw(c670.139,373.754) 672.1,373.754 ; 671.546,366.393 ccw(c670.531,366.393) 671.249,367.111 cw(c669.133,364.995) 672.125,364.995 ; 671.57,335.913 cw(c671.57,334.917) 672.274,335.621 ; 671.604,339.545 ccw(c671.604,340.493) 672.274,339.823 ; 671.673,371.916 cw(c673.015,371.916) 672.066,372.864 ; 671.673,372.292 cw(c672.286,372.292) 672.064,372.863 ; 671.68,360.952 cw(c670.775,359.951) 672.125,359.951 ; 671.687,360.663 ccw(c670.631,361.719) 672.125,361.719 ; 671.693,344.752 ccw(c671.693,345.574) 672.274,344.993 ; 671.772,373.553 cw(c671.087,372.869) 672.055,372.869 ; 672.125,368.476 672.125,361.383 ; 672.252,385.265 671.109,384.122 668.442,384.122 667.578,383.258 667.578,382.369 ; 672.252,386.134 cw(c673.228,386.134) v1@672.538,386.824 ; 672.252,387.444 ccw(c673.228,387.444) v1@672.538,386.754 ; 672.252,392.103 cw(c673.228,392.103) v1@672.538,392.793 ; 672.252,393.413 ccw(c673.228,393.413) v1@672.538,392.723 ; 672.274,344.944 ccw(c671.25,343.92) 671.25,345.369 ccw(c671.25,346.817) 672.274,345.793 ; v1@672.609,386.754 ccw(c672.243,387.119) 672.76,387.119 ; v1@672.609,386.824 cw(c672.243,386.459) 672.76,386.459 ; v1@672.609,392.723 ccw(c672.243,393.088) 672.76,393.088 ; v1@672.609,392.793 cw(c672.243,392.428) 672.76,392.428 ; 673.522,394.384 672.76,393.622 672.76,385.138 672.252,384.63 ; 673.751,379.804 674.538,380.591 674.538,380.82 ; 673.793,372.864 cw(c675.523,371.135) 675.523,373.581 ; 673.795,372.867 ccw(c674.562,372.652) 673.999,372.088 ; 674.067,403.821 ccw(c673.082,404.806) 674.474,404.806 ; 674.474,406.611 cw(c675.519,406.611) 674.78,407.349 ; 674.533,382.514 ccw(c672.683,384.364) 675.3,384.364 ; 674.693,398.348 681.393,398.348 683.049,398.348 683.428,398.727 683.428,403.172 682.843,403.757 681.421,403.757 ; 674.693,401.748 681.393,401.748 ; v1(675.3,392.758) 675.3,382.471 ; 676.125,405.458 677.205,405.458 677.608,405.055 677.608,403.68 ; 676.131,380.82 673.751,380.82 673.751,373.581 ; 676.164,396.035 674.615,396.035 ; 676.697,354.102 676.141,354.658 662.552,354.658 661.965,355.245 661.965,360.048 661.132,360.881 ; 676.874,346.593 ccw(c675.85,347.617) 677.299,347.617 ccw(c678.747,347.617) 677.723,346.593 ; 676.9,407.642 679.783,407.642 ; 677.299,345.369 677.299,348.275 679.11,350.086 ; 677.685,403.757 679.77,403.757 679.77,401.9 ; 677.825,368.12 cw(c677.825,366.793) 678.824,367.667 ; 677.847,380.82 679.618,380.82 681.23,380.82 682.716,380.82 ; 677.949,403.539 cw(c678.477,403.011) 678.477,403.757 ; 678.069,396.035 679.695,396.035 681.219,396.035 682.743,396.035 ; 678.094,358.264 cw(c681.086,358.264) 678.97,360.38 ccw(c679.995,359.355) 678.546,359.355 ccw(c677.097,359.355) 678.122,360.38 ; 678.094,363.344 ccw(c681.086,363.344) 678.97,361.228 cw(c679.688,361.946) 678.673,361.946 ; 678.094,364.689 cw(c681.519,364.689) 679.097,367.111 ccw(c680.122,366.086) 678.673,366.086 ccw(c677.224,366.086) 678.249,367.111 ccw(c677.224,366.086) 677.224,367.535 ccw(c677.224,368.984) 678.249,367.959 ; 678.094,366.62 cw(c679.588,366.62) 678.532,367.676 ; 678.094,366.956 678.094,355.928 678.348,355.674 681.015,355.674 693.08,355.674 ; 678.122,361.228 ccw(c676.791,362.559) 678.673,362.559 ; 678.221,367.14 ccw(c676.062,365.251) 676.062,368.12 ; 678.424,302.97 cw(c677.296,301.706) 678.99,301.706 ; 678.938,355.845 680.843,355.845 694.94,355.845 695.112,355.674 ; 678.99,303.604 678.99,301.706 ; 679.11,356.309 678.546,356.873 678.546,360.804 678.673,360.931 678.673,367.535 ; v1@679.165,339.594 cw(c679.351,338.838) 679.902,339.388 ; v1@679.177,339.595 cw(c679.177,338.345) 680.061,339.229 ; v1@679.211,339.508 ccw(c678.362,340.434) 679.618,340.434 ; 679.556,302.97 ccw(c680.684,301.706) 678.99,301.706 ; 679.618,340.09 cw(c680.568,340.09) v1@679.896,340.761 ; 679.618,340.118 cw(c680.5,340.118) v1@679.897,340.763 ; 679.618,341.362 ccw(c680.568,341.362) v1@679.896,340.691 ; 679.618,345.939 cw(c680.46,345.939) v1@680.105,346.702 ; 679.695,394.384 682.743,394.384 674.615,394.384 672.989,394.384 672.252,393.647 672.252,384.63 ; v1@679.883,340.737 ccw(c681.089,340.479) 680.217,339.607 ; v1@680.076,346.657 cw(c682.408,346.657) v1@680.759,348.306 ; v1@680.121,346.607 cw(c680.179,347.165) v1@679.618,347.165 ; 680.163,339.66 ccw(c681.192,340.688) 681.192,339.234 ; 680.524,348.071 cw(c681.523,347.073) v1@681.523,348.485 ; 680.54,348.087 ccw(c680.191,348.435) v1@680.684,348.435 ; v1@680.571,348.118 cw(c681.461,347.227) v1@681.526,348.485 ; 680.634,339.189 679.618,340.205 679.618,340.434 ; v1@680.716,347.397 cw(c681.527,347.796) v1@680.888,348.435 ; 681.192,339.189 680.101,339.189 679.618,339.672 679.618,340.434 ; 681.192,340.84 681.192,345.945 682.031,346.784 694.683,346.784 695.826,347.927 ; 681.192,345.26 682.208,346.276 682.666,346.276 ; 681.339,347.87 ccw(c680.774,348.435) v1@681.573,348.435 ; 681.523,346.276 682.666,346.276 ; 681.948,371.251 695.112,371.251 695.747,370.616 ; 682.437,378.204 682.437,380.541 ; 682.437,380.094 cw(c683.404,380.094) 682.721,380.777 ; 682.913,398.212 cw(c684.063,397.061) v1@684.063,398.688 ; 683.066,398.365 cw(c683.882,397.549) v1@684.071,398.687 ; 683.174,370.787 680.38,373.581 673.751,373.581 ; 683.428,400.05 ccw(c685.475,400.05) v1@684.028,398.603 ; 684.273,382.471 ccw(c684.273,383.218) v1@684.801,382.69 ; 684.677,303.604 684.677,307.054 683.682,308.049 658.663,308.049 657.749,308.963 657.749,320.622 ; v1@684.73,382.69 ccw(c685.258,383.218) 685.258,382.471 ; v1@686.476,382.725 686.222,382.471 682.716,382.471 681.23,382.471 679.618,382.471 675.3,382.471 ; v1(688.381,379.169) 688.381,377.817 688.49,377.709 690.413,377.709 ; 688.566,377.938 ccw(c689.121,378.493) 689.121,377.709 ; 692.924,352.626 ccw(c692.05,352.626) 692.668,353.244 ccw(c693.286,353.862) 693.286,352.988 ; 693.618,300.683 cw(c693.618,299.503) v1@694.453,300.337 ; v1@694.382,300.337 cw(c695.216,299.503) 695.216,300.683 ; 694.606,378.053 cw(c693.753,377.2) 694.96,377.2 cw(c696.167,377.2) 695.314,378.053 ; 694.858,341.133 696.382,341.133 697.906,341.133 699.43,341.133 700.954,341.133 ; v1@694.96,376.756 694.96,378.407 ; 694.994,353.76 cw(c693.861,352.626) 695.464,352.626 ; 695.57,349.83 cw(c694.952,349.212) 695.826,349.212 cw(c696.7,349.212) 696.082,349.83 ; 695.57,352.882 ccw(c694.952,353.5) 695.826,353.5 ccw(c696.7,353.5) 696.082,352.882 ; 695.826,350.086 695.826,347.244 694.858,346.276 682.666,346.276 ; 695.826,352.626 695.826,352.928 ; 699.108,302.973 cw(c697.952,301.692) 699.677,301.692 ; 699.677,303.604 699.677,301.692 ; 700.246,302.973 ccw(c701.402,301.692) 699.677,301.692 ; 705.914,374.082 ccw(c705.316,374.68) 706.161,374.68 ccw(c707.006,374.68) 706.408,374.082 ; 706.161,373.835 706.161,375.359 706.796,375.994 707.558,375.994 ; 706.411,374.08 cw(c706.803,374.463) 706.415,374.851 707.558,375.994 ; 706.511,373.835 cw(c709.196,373.835) 707.297,375.733 ; 708.948,374.082 ccw(c709.546,374.68) 709.546,373.835 ccw(c709.546,372.99) 708.948,373.588 ; 709.019,374.153 cw(c708.254,373.388) 709.336,373.388 ; v1@709.178,375.955 ccw(c709.489,376.349) 709.844,375.994 v1@710.758,376.908 ; v1@709.209,375.944 ccw(c709.209,377.356) 710.208,376.358 ; v1@709.301,376.086 cw(c710.733,374.653) 710.733,376.679 ccw(c710.733,376.186) 710.385,376.535 ; v1@709.321,375.994 ccw(c709.321,378.041) v1@710.768,376.594 ; 709.336,371.457 ccw(c706.323,371.457) 708.454,373.588 ; v1@709.654,376.439 cw(c710.386,375.706) v1@710.751,376.676 ; v1@709.798,376.609 ccw(c710.733,377.012) v1(710.733,375.994) ; v1@709.839,376.579 ccw(c709.951,377.715) v1@710.758,376.908 ; v1@709.879,376.594 ccw(c709.351,377.122) 710.098,377.122 ; v1@709.887,376.604 cw(c708.828,377.219) 708.828,375.994 ; 709.971,373.835 709.336,373.2 709.336,371.295 708.656,370.616 706.923,370.616 ; v1@710.098,376.783 cw(c711.371,376.783) 710.859,377.949 ; v1@710.693,375.964 cw(c711.267,376.399) v1@710.758,376.908 ; v1@710.704,376.588 cw(c711.509,377.747) 710.098,377.747 710.098,376.883 v1(709.209,375.994) 708.828,375.994 ; 725.528,375.613 v1(726.354,375.613) 727.179,375.613 ; 725.528,377.01 v1(726.354,377.01) 727.179,377.01 ; 728.83,377.01 728.83,375.613 728.83,374.407 ; 729.032,374.407 cw(c729.032,372.576) v1@730.326,373.87 ; 729.603,373.835 ccw(c729.603,375.666) v1@730.898,374.371 ; 729.667,374.407 cw(c729.667,372.576) v1@730.961,373.87 ; v1@730.241,373.84 cw(c730.862,373.783) v1(730.862,374.407) ; v1@730.652,374.617 cw(c729.87,373.835) v1@730.976,373.835 ; v1@742.941,373.84 cw(c743.499,373.782) 743.499,374.343 ; v1@742.956,373.87 cw(c744.097,372.729) v1@744.097,374.343 ; 742.974,307.285 758.764,307.285 ; v1@743.068,371.427 cw(c743.626,371.369) v1@743.626,371.93 ; v1@743.083,371.457 cw(c744.224,370.316) v1@744.224,371.93 ; v1@743.282,371.422 ccw(c743.282,373.036) v1@744.423,371.895 ; 743.398,306.861 cw(c744.423,305.836) 744.423,307.285 cw(c744.423,308.734) 743.398,307.709 ; v1@743.464,371.895 ccw(c744.605,373.036) 744.605,371.422 ; v1@743.718,373.87 cw(c744.859,372.729) 744.859,374.343 ; v1@743.845,371.457 cw(c744.986,370.316) 744.986,371.93 ; v1@743.972,374.435 ccw(c745.419,375.882) 745.419,373.835 ; v1@744.05,374.445 cw(c742.991,375.06) v1(742.991,373.835) ; v1@744.353,371.895 ccw(c745.494,373.036) 745.494,371.422 ; 746.906,378.179 cw(c748.683,378.348) 747.42,379.61 ; 746.958,371.93 cw(c746.958,370.75) v1@747.793,371.584 ; 747.055,376.981 cw(c748.566,376.981) 747.497,378.05 ; 747.055,377.772 747.055,379.244 ; 747.426,378.6 cw(c747.801,379.244) 747.055,379.244 ; 747.453,378.05 cw(c746.855,377.452) 747.7,377.452 cw(c748.545,377.452) 747.947,378.05 ; 747.453,378.544 ccw(c746.855,379.142) 747.7,379.142 ccw(c748.545,379.142) 747.947,378.544 ; 747.702,378.254 cw(c750.877,378.556) 748.622,380.811 ; v1@747.722,371.584 cw(c748.556,370.75) 748.556,371.93 ; 748.15,378.647 ccw(c748.15,380.262) 749.292,379.12 ; 748.413,380.019 ccw(c750.136,378.297) 747.7,378.297 ; 748.469,378.297 749.824,379.652 v1(749.824,380.693) ; 748.498,378.33 cw(c753.072,378.764) 749.823,382.013 ; 748.651,380.258 cw(c749.824,379.085) v1@749.824,380.743 ; 749.066,379.663 ccw(c750.431,378.297) 748.5,378.297 cw(c752.867,378.297) 749.779,381.385 ; 749.335,380.941 ccw(c748.263,382.013) 749.779,382.013 ; 749.776,385.202 749.776,388.315 ; v1@749.785,380.661 cw(c750.229,381.024) 749.824,381.43 747.7,379.306 747.7,378.297 ; 749.824,383.503 749.824,382.013 ; 751.235,381.085 cw(c748.448,378.297) 752.39,378.297 ccw(c750.459,378.297) 751.824,379.663 ; 751.475,380.845 753.19,379.13 ; 751.5,388.388 751.475,388.363 751.475,382.013 ; 751.519,382.013 ccw(c752.667,382.013) 751.855,381.201 ; v1@751.857,374.435 ccw(c750.264,376.027) 752.516,376.027 ; v1@751.857,374.505 cw(c750.264,372.913) 752.516,372.913 ; 752.08,380.976 cw(c749.401,378.297) 753.19,378.297 ; 752.516,376.911 cw(c754.126,376.911) 752.987,378.05 ; 752.516,378.971 752.516,373.073 751.373,371.93 750.992,371.93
